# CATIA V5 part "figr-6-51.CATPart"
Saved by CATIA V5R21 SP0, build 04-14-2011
Part number: Part1
Bounding box of the stored display mesh (mm): x -46.66 to 43.071, y -43.071 to 47.059, z 0 to 20
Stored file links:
  D:\CATIA V5R21 E-RESOURCES\CATIA-V5R21\catia-v5r21-prt\c06-catia-v5r21-prt\c06-catia-v5r21-figr-6-51.CATPart
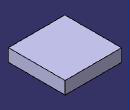
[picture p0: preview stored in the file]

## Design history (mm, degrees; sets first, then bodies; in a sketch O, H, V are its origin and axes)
Body1 (main body)
  Sketch1 on xy-plane, origin (0, 0, 0), H (1, 0, 0), V (0, 1, 0)
    line L1 (-46.6598, 47.0586) -> (43.0706, 47.0586)
    line L2 (43.0706, 47.0586) -> (43.0706, -43.0706)
    line L3 (43.0706, -43.0706) -> (-46.6598, -43.0706)
    line L4 (-46.6598, -43.0706) -> (-46.6598, 47.0586)
    horizontal: L1 H, L3 H
    vertical: L2 V, L4 V
  Pad1: profile Sketch1, direction (0, 0, 1), length 20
